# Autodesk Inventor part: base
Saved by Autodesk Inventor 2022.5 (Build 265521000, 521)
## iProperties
Created: 2024-12
Part Number: base
Material: Generic
Document SubType Name: Modeling
Designer: AdminForWorker
Density: 1 g/cm^3
Appearance: Default
Title: base
Author: AdminForWorker
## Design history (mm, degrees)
feature "Body1"
body "Solid1"
